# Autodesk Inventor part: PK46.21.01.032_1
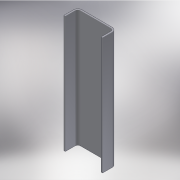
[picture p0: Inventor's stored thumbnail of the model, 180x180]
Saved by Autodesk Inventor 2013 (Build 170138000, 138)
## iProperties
Created: 2005-03
Part Number: PK46.21.01.032_1
Material: Steel, Mild
Document SubType Name: Sheet Metal
Designer: salex
Manufacturer: Standard
Standards Organization: Custom
Density: 7.86 g/cm^3
Sheet Metal Rule: Default
Author: salex
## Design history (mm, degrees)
node "ФлнОтгиб1"
body "Solid1"
sketch "Эскиз1"
  geometry: L1 (0, 0)-(0, 90); L2 (0, 90)-(260, 90); L3 (260, 90)-(260, 0)
  constraints: 6 end point, 2 parallel, 1 perpendicular, 1 vertical, 1 other
  dimensions: "d0" = 260 distance of L1.end L2.end; "d1" = 90 distance of L1.start L1.end
feature "Плакирование1" dims "d2" = 850, "d3" = 10 (= BendReliefWidth), "d5" = 20 (= MinimumRemnant), "d7" = 20 (= BendRadius), "d8" = 10, "Thickness" = 10
feature "Изгиб1" dims "d3" = 10 (= BendReliefWidth), "d4" = 5 (= BendReliefDepth), "d5" = 20 (= MinimumRemnant), "d6" = 20 (= BendRadius), "d7" = 20 (= BendRadius), "d8" = 10, "SeamGap" = 0.01, "Thickness" = 10
other parameters: "BendRadius" = 20, "BendReliefDepth" = 5 (= 0.5 x Thickness)
